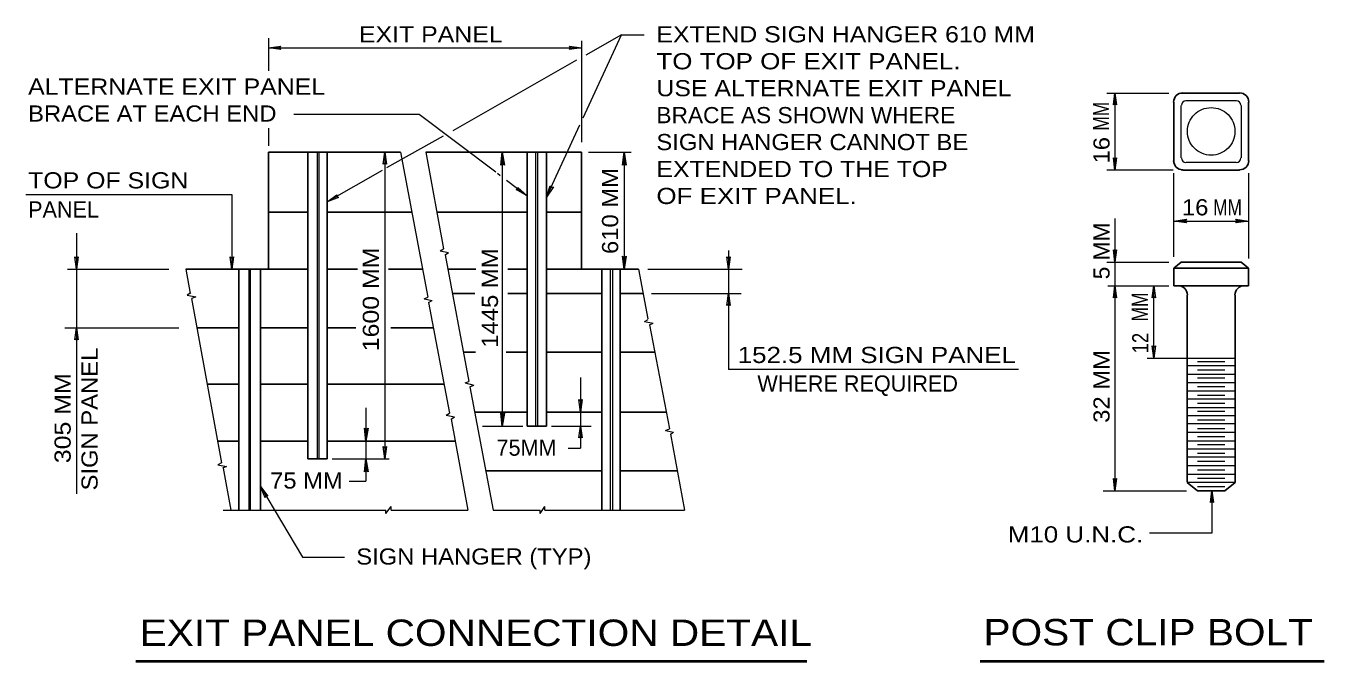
# Model space of a CAD drawing. Extents: x 312601.858 to 312602.699, y 144420.109 to 144420.704.
# Drawn here: x 312602.264 to 312602.5049, y 144420.2749 to 144420.3927 of the extents above; entities that cross this region are included whole.
import ezdxf
from ezdxf.enums import TextEntityAlignment as Align

# ---------------------------------------------------------------- set-up
doc = ezdxf.new("R2010")
doc.units = 0
doc.header["$LTSCALE"] = 0.0012
doc.linetypes.add('LONG_DASHED', pattern=[7.5, 6, -1.5])
for name, color, linetype, lineweight in [('1', 7, 'Continuous', 13), ('2', 7, 'Continuous', 13), ('39', 7, 'Continuous', 13)]:
    doc.layers.add(name, color=color, linetype=linetype, lineweight=lineweight)

msp = doc.modelspace()

# ---------------------------------------------------------------- hatches: boundary and pattern name
at = {"layer": '39'}
for points in [[(312602.3524, 144420.3671), (312602.3521, 144420.3669), (312602.3524, 144420.3693), (312602.3528, 144420.3669)], [(312602.375, 144420.3671), (312602.3747, 144420.3669), (312602.375, 144420.3693), (312602.3754, 144420.3669)], [(312602.4792, 144420.3565), (312602.4794, 144420.3562), (312602.477, 144420.3565), (312602.4794, 144420.3569)], [(312602.4887, 144420.3565), (312602.4885, 144420.3569), (312602.4909, 144420.3565), (312602.4885, 144420.3562)], [(312602.375, 144420.3498), (312602.3754, 144420.35), (312602.375, 144420.3476), (312602.3747, 144420.35)], [(312602.3524, 144420.3207), (312602.3528, 144420.3209), (312602.3524, 144420.3185), (312602.3521, 144420.3209)], [(312602.3271, 144420.3179), (312602.3275, 144420.3181), (312602.3271, 144420.3157), (312602.3268, 144420.3181)], [(312602.3271, 144420.3102), (312602.3268, 144420.31), (312602.3271, 144420.3124), (312602.3275, 144420.31)]]:
    msp.add_hatch(color=256, dxfattribs=at).paths.add_polyline_path(points)

# ---------------------------------------------------------------- linework, layer by layer
at = {"layer": '1'}
for p, q in [((312602.3674, 144420.3757), (312602.3745, 144420.3911)), ((312602.3745, 144420.3911), (312602.3679, 144420.3873)), ((312602.3745, 144420.3911), (312602.3787, 144420.3911)), ((312602.309, 144420.3905), (312602.309, 144420.3844)), ((312602.309, 144420.3887), (312602.3671, 144420.3887)), ((312602.3671, 144420.39), (312602.3671, 144420.3712)), ((312602.3662, 144420.3864), (312602.3432, 144420.3733)), ((312602.4646, 144420.3803), (312602.4761, 144420.3803)), ((312602.4661, 144420.3803), (312602.4661, 144420.366)), ((312602.4784, 144420.3803), (312602.4892, 144420.3803)), ((312602.4793, 144420.3789), (312602.4886, 144420.3789)), ((312602.4909, 144420.3787), (312602.4909, 144420.3674)), ((312602.3137, 144420.3764), (312602.337, 144420.3764)), ((312602.4784, 144420.3683), (312602.4784, 144420.378)), ((312602.4895, 144420.378), (312602.4895, 144420.3683)), ((312602.3606, 144420.361), (312602.3668, 144420.3744)), ((312602.309, 144420.3738), (312602.309, 144420.3705)), ((312602.3414, 144420.3723), (312602.3309, 144420.3664)), ((312602.3306, 144420.3693), (312602.3306, 144420.3124)), ((312602.3335, 144420.3693), (312602.3386, 144420.3424)), ((312602.3382, 144420.3693), (312602.3415, 144420.3514)), ((312602.3524, 144420.3693), (312602.3524, 144420.3185)), ((312602.3684, 144420.3693), (312602.3763, 144420.3693)), ((312602.375, 144420.3693), (312602.375, 144420.3476)), ((312602.4886, 144420.3674), (312602.4793, 144420.3674)), ((312602.3301, 144420.3659), (312602.3199, 144420.3601)), ((312602.4769, 144420.366), (312602.4646, 144420.366)), ((312602.477, 144420.3499), (312602.477, 144420.3654)), ((312602.4893, 144420.366), (312602.4784, 144420.366)), ((312602.4909, 144420.3654), (312602.4909, 144420.3496)), ((312602.264, 144420.3615), (312602.3022, 144420.3615)), ((312602.3022, 144420.3615), (312602.3022, 144420.3476)), ((312602.477, 144420.3565), (312602.4909, 144420.3565)), ((312602.3409, 144420.351), (312602.3415, 144420.3514)), ((312602.3409, 144420.351), (312602.3424, 144420.3507)), ((312602.3418, 144420.3503), (312602.3424, 144420.3507)), ((312602.3418, 144420.3503), (312602.3462, 144420.3268)), ((312602.3944, 144420.3511), (312602.3944, 144420.3431)), ((312602.2717, 144420.3476), (312602.2905, 144420.3476)), ((312602.2937, 144420.3476), (312602.2945, 144420.3431)), ((312602.3777, 144420.3476), (312602.3794, 144420.3384)), ((312602.3794, 144420.3476), (312602.3969, 144420.3476)), ((312602.4646, 144420.3489), (312602.4761, 144420.3489)), ((312602.3801, 144420.3431), (312602.3967, 144420.3431)), ((312602.3944, 144420.3431), (312602.3944, 144420.329)), ((312602.4648, 144420.3445), (312602.4761, 144420.3445)), ((312602.4733, 144420.3311), (312602.4733, 144420.3445)), ((312602.2947, 144420.3422), (312602.3003, 144420.3117)), ((312602.3379, 144420.3421), (312602.3386, 144420.3424)), ((312602.3379, 144420.3421), (312602.3394, 144420.3418)), ((312602.3387, 144420.3414), (312602.3394, 144420.3418)), ((312602.3387, 144420.3414), (312602.3426, 144420.3209)), ((312602.3788, 144420.3379), (312602.3795, 144420.3383)), ((312602.3788, 144420.3379), (312602.3804, 144420.3376)), ((312602.2712, 144420.3367), (312602.2924, 144420.3367)), ((312602.2734, 144420.3367), (312602.2734, 144420.3059)), ((312602.3797, 144420.3373), (312602.3804, 144420.3376)), ((312602.3797, 144420.3373), (312602.3834, 144420.318)), ((312602.4721, 144420.3311), (312602.4884, 144420.3311)), ((312602.4482, 144420.329), (312602.3944, 144420.329)), ((312602.4884, 144420.3297), (312602.4795, 144420.3297)), ((312602.4884, 144420.3281), (312602.4795, 144420.3281)), ((312602.4865, 144420.3304), (312602.4814, 144420.3304)), ((312602.4865, 144420.3289), (312602.4814, 144420.3289)), ((312602.3455, 144420.3265), (312602.3462, 144420.3268)), ((312602.3455, 144420.3265), (312602.3471, 144420.3261)), ((312602.3464, 144420.3258), (312602.3471, 144420.3261)), ((312602.3464, 144420.3258), (312602.3507, 144420.3029)), ((312602.4884, 144420.3265), (312602.4795, 144420.3265)), ((312602.4865, 144420.3274), (312602.4814, 144420.3274)), ((312602.4865, 144420.3258), (312602.4814, 144420.3258)), ((312602.4884, 144420.325), (312602.4795, 144420.325)), ((312602.4884, 144420.3235), (312602.4795, 144420.3235)), ((312602.4865, 144420.3242), (312602.4814, 144420.3242)), ((312602.342, 144420.3205), (312602.3426, 144420.3209)), ((312602.4884, 144420.3219), (312602.4795, 144420.3219)), ((312602.4865, 144420.3227), (312602.4814, 144420.3227)), ((312602.4865, 144420.3212), (312602.4814, 144420.3212)), ((312602.342, 144420.3205), (312602.3435, 144420.3202)), ((312602.3429, 144420.3198), (312602.3435, 144420.3202)), ((312602.3429, 144420.3198), (312602.346, 144420.3029)), ((312602.3487, 144420.3185), (312602.3562, 144420.3185)), ((312602.3615, 144420.3185), (312602.3689, 144420.3185)), ((312602.4884, 144420.3204), (312602.4795, 144420.3204)), ((312602.4884, 144420.3189), (312602.4795, 144420.3189)), ((312602.4865, 144420.3196), (312602.4814, 144420.3196)), ((312602.3827, 144420.3177), (312602.3834, 144420.318)), ((312602.3827, 144420.3177), (312602.3842, 144420.3174)), ((312602.3836, 144420.317), (312602.3842, 144420.3174)), ((312602.3836, 144420.317), (312602.3862, 144420.3029)), ((312602.4884, 144420.3173), (312602.4795, 144420.3173)), ((312602.4865, 144420.318), (312602.4814, 144420.318)), ((312602.4865, 144420.3165), (312602.4814, 144420.3165)), ((312602.4884, 144420.3157), (312602.4795, 144420.3157)), ((312602.4884, 144420.3142), (312602.4795, 144420.3142)), ((312602.4865, 144420.315), (312602.4814, 144420.315)), ((312602.3208, 144420.3124), (312602.3314, 144420.3124)), ((312602.3271, 144420.3124), (312602.3271, 144420.3083)), ((312602.4884, 144420.3127), (312602.4795, 144420.3127)), ((312602.4865, 144420.3134), (312602.4814, 144420.3134)), ((312602.4865, 144420.3119), (312602.4814, 144420.3119)), ((312602.3006, 144420.3107), (312602.302, 144420.3029)), ((312602.4884, 144420.3111), (312602.4795, 144420.3111)), ((312602.4884, 144420.3095), (312602.4795, 144420.3095)), ((312602.4865, 144420.3103), (312602.4814, 144420.3103)), ((312602.3075, 144420.3073), (312602.3153, 144420.2942)), ((312602.4639, 144420.3065), (312602.4794, 144420.3065)), ((312602.4884, 144420.308), (312602.4795, 144420.308)), ((312602.4865, 144420.3088), (312602.4814, 144420.3088)), ((312602.4865, 144420.3072), (312602.4814, 144420.3072)), ((312602.3006, 144420.3029), (312602.3308, 144420.3029)), ((312602.3308, 144420.3023), (312602.3318, 144420.3036)), ((312602.3308, 144420.3023), (312602.3308, 144420.3029)), ((312602.3318, 144420.3029), (312602.3318, 144420.3036)), ((312602.3318, 144420.3029), (312602.346, 144420.3029)), ((312602.3507, 144420.3029), (312602.3594, 144420.3029)), ((312602.3594, 144420.3023), (312602.3603, 144420.3036)), ((312602.3594, 144420.3023), (312602.3594, 144420.3029)), ((312602.3603, 144420.3029), (312602.3603, 144420.3036)), ((312602.3603, 144420.3029), (312602.3862, 144420.3029)), ((312602.3153, 144420.2942), (312602.3231, 144420.2942))]:
    msp.add_line(p, q, dxfattribs=at)
at = {"layer": '1', "lineweight": 25}
for p, q in [((312602.4787, 144420.3803), (312602.4892, 144420.3803)), ((312602.477, 144420.3676), (312602.477, 144420.3786)), ((312602.4909, 144420.3786), (312602.4909, 144420.3677)), ((312602.309, 144420.3693), (312602.309, 144420.3476)), ((312602.309, 144420.3693), (312602.3335, 144420.3693)), ((312602.3163, 144420.3693), (312602.3163, 144420.3124)), ((312602.3199, 144420.3693), (312602.3199, 144420.3124)), ((312602.3382, 144420.3693), (312602.3671, 144420.3693)), ((312602.357, 144420.3693), (312602.357, 144420.3185)), ((312602.3606, 144420.3693), (312602.3606, 144420.3185)), ((312602.3671, 144420.3693), (312602.3671, 144420.3476)), ((312602.4787, 144420.366), (312602.4892, 144420.366)), ((312602.309, 144420.3582), (312602.3163, 144420.3582)), ((312602.3199, 144420.3582), (312602.3356, 144420.3582)), ((312602.3403, 144420.3582), (312602.357, 144420.3582)), ((312602.3606, 144420.3582), (312602.3671, 144420.3582)), ((312602.2937, 144420.3476), (312602.3163, 144420.3476)), ((312602.3035, 144420.3476), (312602.3035, 144420.3029)), ((312602.3075, 144420.3476), (312602.3075, 144420.3029)), ((312602.3199, 144420.3476), (312602.3255, 144420.3476)), ((312602.3313, 144420.3476), (312602.3375, 144420.3476)), ((312602.3423, 144420.3476), (312602.3475, 144420.3476)), ((312602.3534, 144420.3476), (312602.357, 144420.3476)), ((312602.3606, 144420.3476), (312602.3777, 144420.3476)), ((312602.3709, 144420.3476), (312602.3709, 144420.3029)), ((312602.3743, 144420.3476), (312602.3743, 144420.3029)), ((312602.477, 144420.3478), (312602.4784, 144420.3489)), ((312602.477, 144420.3445), (312602.477, 144420.3478)), ((312602.477, 144420.3478), (312602.4909, 144420.3478)), ((312602.4784, 144420.3489), (312602.4895, 144420.3489)), ((312602.4895, 144420.3489), (312602.4909, 144420.3478)), ((312602.4909, 144420.3478), (312602.4909, 144420.3445)), ((312602.3431, 144420.3431), (312602.3473, 144420.3431)), ((312602.3534, 144420.3431), (312602.357, 144420.3431)), ((312602.3606, 144420.3431), (312602.3709, 144420.3431)), ((312602.3743, 144420.3431), (312602.3786, 144420.3431)), ((312602.477, 144420.3445), (312602.4909, 144420.3445)), ((312602.4795, 144420.3428), (312602.4795, 144420.3081)), ((312602.4884, 144420.3428), (312602.4884, 144420.308)), ((312602.2957, 144420.3367), (312602.3035, 144420.3367)), ((312602.3075, 144420.3367), (312602.3163, 144420.3367)), ((312602.3199, 144420.3367), (312602.3252, 144420.3367)), ((312602.3317, 144420.3367), (312602.3397, 144420.3367)), ((312602.3452, 144420.3322), (312602.3474, 144420.3322)), ((312602.3531, 144420.3322), (312602.357, 144420.3322)), ((312602.3606, 144420.3322), (312602.3709, 144420.3322)), ((312602.3743, 144420.3322), (312602.3806, 144420.3322)), ((312602.2976, 144420.3263), (312602.3035, 144420.3263)), ((312602.3075, 144420.3263), (312602.3163, 144420.3263)), ((312602.3199, 144420.3263), (312602.3416, 144420.3263)), ((312602.3473, 144420.3211), (312602.357, 144420.3211)), ((312602.3606, 144420.3211), (312602.3709, 144420.3211)), ((312602.3743, 144420.3211), (312602.3828, 144420.3211)), ((312602.357, 144420.3185), (312602.3606, 144420.3185)), ((312602.2996, 144420.3157), (312602.3035, 144420.3157)), ((312602.3075, 144420.3157), (312602.3163, 144420.3157)), ((312602.3199, 144420.3157), (312602.3437, 144420.3157)), ((312602.3163, 144420.3124), (312602.3199, 144420.3124)), ((312602.3494, 144420.3102), (312602.3709, 144420.3102)), ((312602.3743, 144420.3102), (312602.3849, 144420.3102)), ((312602.4814, 144420.3065), (312602.4795, 144420.308)), ((312602.4814, 144420.3065), (312602.4865, 144420.3065)), ((312602.4865, 144420.3065), (312602.4884, 144420.308))]:
    msp.add_line(p, q, dxfattribs=at)
at = {"layer": '1'}
for points in [[(312602.3113, 144420.3884), (312602.309, 144420.3887), (312602.3113, 144420.389), (312602.311, 144420.3887)], [(312602.3649, 144420.389), (312602.3671, 144420.3887), (312602.3649, 144420.3884), (312602.3651, 144420.3887)], [(312602.4658, 144420.3781), (312602.4661, 144420.3803), (312602.4664, 144420.3781), (312602.4661, 144420.3783)], [(312602.3303, 144420.3671), (312602.3306, 144420.3693), (312602.3309, 144420.3671), (312602.3306, 144420.3673)], [(312602.4664, 144420.3683), (312602.4661, 144420.366), (312602.4658, 144420.3683), (312602.4661, 144420.368)], [(312602.3553, 144420.3628), (312602.357, 144420.3612), (312602.355, 144420.3624), (312602.3554, 144420.3624)], [(312602.3619, 144420.3629), (312602.3606, 144420.361), (312602.3613, 144420.3631), (312602.3615, 144420.3628)], [(312602.322, 144420.3609), (312602.3199, 144420.3601), (312602.3217, 144420.3614), (312602.3217, 144420.3611)], [(312602.2737, 144420.3499), (312602.2734, 144420.3476), (312602.2731, 144420.3499), (312602.2734, 144420.3496)], [(312602.3025, 144420.3499), (312602.3022, 144420.3476), (312602.3019, 144420.3499), (312602.3022, 144420.3496)], [(312602.3947, 144420.3499), (312602.3944, 144420.3476), (312602.3941, 144420.3499), (312602.3944, 144420.3496)], [(312602.4664, 144420.3512), (312602.4661, 144420.3489), (312602.4658, 144420.3512), (312602.4661, 144420.3509)], [(312602.3941, 144420.3409), (312602.3944, 144420.3431), (312602.3947, 144420.3409), (312602.3944, 144420.3411)], [(312602.4658, 144420.3423), (312602.4661, 144420.3445), (312602.4664, 144420.3423), (312602.4661, 144420.3425)], [(312602.473, 144420.3423), (312602.4733, 144420.3445), (312602.4736, 144420.3423), (312602.4733, 144420.3425)], [(312602.2731, 144420.3345), (312602.2734, 144420.3367), (312602.2737, 144420.3345), (312602.2734, 144420.3347)], [(312602.4736, 144420.3334), (312602.4733, 144420.3311), (312602.473, 144420.3334), (312602.4733, 144420.3331)], [(312602.3672, 144420.3234), (312602.3669, 144420.3211), (312602.3666, 144420.3234), (312602.3669, 144420.3231)], [(312602.3666, 144420.3163), (312602.3669, 144420.3185), (312602.3672, 144420.3163), (312602.3669, 144420.3165)], [(312602.3309, 144420.3147), (312602.3306, 144420.3124), (312602.3303, 144420.3147), (312602.3306, 144420.3144)], [(312602.3084, 144420.3052), (312602.3075, 144420.3073), (312602.3089, 144420.3055), (312602.3085, 144420.3056)], [(312602.4664, 144420.3088), (312602.4661, 144420.3065), (312602.4658, 144420.3088), (312602.4661, 144420.3085)], [(312602.4838, 144420.3043), (312602.4841, 144420.3065), (312602.4844, 144420.3043), (312602.4841, 144420.3045)]]:
    msp.add_lwpolyline(points, close=True, dxfattribs=at)
for points in [[(312602.4661, 144420.357), (312602.4661, 144420.3489), (312602.4661, 144420.3445), (312602.4661, 144420.3065)], [(312602.2734, 144420.3543), (312602.2734, 144420.3476), (312602.2734, 144420.3367)], [(312602.3669, 144420.3275), (312602.3669, 144420.3211), (312602.3669, 144420.3185), (312602.3669, 144420.3144)], [(312602.3271, 144420.3219), (312602.3271, 144420.3157), (312602.3271, 144420.3124)], [(312602.4841, 144420.3065), (312602.4841, 144420.2986), (312602.4725, 144420.2986)]]:
    msp.add_lwpolyline(points, dxfattribs=at)
at = {"layer": '1', "linetype": 'LONG_DASHED'}
msp.add_circle((312602.483955, 144420.373185), 0.00442, dxfattribs=at)
at = {"layer": '1', "lineweight": 25}
for centre, start, end in [((312602.478685, 144420.378625), 90, 180), ((312602.489225, 144420.378625), 0, 90.00156), ((312602.478685, 144420.367745), 180, 270), ((312602.489225, 144420.367745), 270, 359.99844), ((312602.477835, 144420.342845), 0, 90), ((312602.490075, 144420.342845), 90, 180)]:
    msp.add_arc(centre, 0.0017, start, end, dxfattribs=at)
at = {"layer": '1'}
for centre, start, end in [((312602.47928, 144420.37803), 90, 180), ((312602.48863, 144420.37803), 0, 90), ((312602.47928, 144420.368255), 180, 270), ((312602.48863, 144420.368255), 270, 0)]:
    msp.add_arc(centre, 0.00085, start, end, dxfattribs=at)
at = {"layer": '2'}
for p, q in [((312602.337, 144420.3764), (312602.3512, 144420.3657)), ((312602.3515, 144420.3654), (312602.352, 144420.365)), ((312602.3532, 144420.3641), (312602.357, 144420.3612)), ((312602.3646, 144420.3144), (312602.3669, 144420.3144)), ((312602.324, 144420.3083), (312602.3271, 144420.3083))]:
    msp.add_line(p, q, dxfattribs=at)
at = {"layer": '2', "linetype": 'LONG_DASHED'}
for p, q in [((312602.3181, 144420.3124), (312602.3181, 144420.3693)), ((312602.3184, 144420.3124), (312602.3184, 144420.3693)), ((312602.3586, 144420.3184), (312602.3586, 144420.3693)), ((312602.359, 144420.3185), (312602.359, 144420.3693)), ((312602.3054, 144420.3029), (312602.3054, 144420.3476)), ((312602.3057, 144420.3029), (312602.3057, 144420.3476)), ((312602.3725, 144420.3029), (312602.3725, 144420.3476)), ((312602.3729, 144420.3029), (312602.3729, 144420.3476))]:
    msp.add_line(p, q, dxfattribs=at)
at = {"layer": '2', "lineweight": 40}
for p, q in [((312602.2844, 144420.2749), (312602.4089, 144420.2749)), ((312602.4411, 144420.2749), (312602.5049, 144420.2749))]:
    msp.add_line(p, q, dxfattribs=at)
at = {"layer": '2'}
for points in [[(312602.2946, 144420.3432), (312602.2939, 144420.3428), (312602.2955, 144420.3425), (312602.2948, 144420.3422)], [(312602.3003, 144420.3117), (312602.2996, 144420.3113), (312602.3012, 144420.311), (312602.3005, 144420.3107)]]:
    msp.add_lwpolyline(points, dxfattribs=at)
at = {"layer": '39'}
for points in [[(312602.3524, 144420.3671), (312602.3521, 144420.3669), (312602.3524, 144420.3693), (312602.3528, 144420.3669)], [(312602.375, 144420.3671), (312602.3747, 144420.3669), (312602.375, 144420.3693), (312602.3754, 144420.3669)], [(312602.4792, 144420.3565), (312602.4794, 144420.3562), (312602.477, 144420.3565), (312602.4794, 144420.3569)], [(312602.4887, 144420.3565), (312602.4885, 144420.3569), (312602.4909, 144420.3565), (312602.4885, 144420.3562)], [(312602.375, 144420.3498), (312602.3754, 144420.35), (312602.375, 144420.3476), (312602.3747, 144420.35)], [(312602.3524, 144420.3207), (312602.3528, 144420.3209), (312602.3524, 144420.3185), (312602.3521, 144420.3209)], [(312602.3271, 144420.3179), (312602.3275, 144420.3181), (312602.3271, 144420.3157), (312602.3268, 144420.3181)], [(312602.3271, 144420.3102), (312602.3268, 144420.31), (312602.3271, 144420.3124), (312602.3275, 144420.31)]]:
    msp.add_lwpolyline(points, close=True, dxfattribs=at)

# ---------------------------------------------------------------- texts
at = {"layer": '2'}
for s, height, width, p in [('EXIT PANEL', 0.003, 1.15, (312602.3258, 144420.3897)), ('EXTEND SIGN HANGER 610 MM', 0.003, 1.15, (312602.381, 144420.3897)), ('TO TOP OF EXIT PANEL.', 0.003, 1.2, (312602.381, 144420.3847)), ('ALTERNATE EXIT PANEL', 0.003, 1.15, (312602.2644, 144420.38)), ('USE ALTERNATE EXIT PANEL', 0.003, 1.15, (312602.381, 144420.3797)), ('BRACE AT EACH END', 0.003, 1.1, (312602.2644, 144420.375)), ('BRACE AS SHOWN WHERE', 0.003, 1.05, (312602.381, 144420.3747)), ('SIGN HANGER CANNOT BE', 0.003, 1.1, (312602.381, 144420.3697)), ('EXTENDED TO THE TOP', 0.003, 1.15, (312602.381, 144420.3647)), ('TOP OF SIGN', 0.003, 1.15, (312602.2644, 144420.3626)), ('OF EXIT PANEL.', 0.003, 1.2, (312602.381, 144420.3597)), ('M10 U.N.C.', 0.003, 1.2, (312602.4462, 144420.2969)), ('SIGN HANGER (TYP)', 0.003, 1.1, (312602.3253, 144420.2928)), ('EXIT PANEL CONNECTION DETAIL', 0.0049, 1.15, (312602.2851, 144420.2777)), ('POST CLIP BOLT', 0.0049, 1.15, (312602.4417, 144420.2778))]:
    msp.add_text(s, height=height, dxfattribs=dict(at, width=width)).set_placement(p)
for s, width, p in [('MM', 0.8, (312602.465, 144420.376)), ('16 ', 1.1, (312602.4651, 144420.3703)), ('610 MM', 1.1, (312602.3739, 144420.3584)), ('5 MM', 1.05, (312602.4651, 144420.351)), ('1600 MM', 1.15, (312602.3295, 144420.342)), ('1445 MM', 1.1, (312602.3516, 144420.34225)), ('MM', 0.8, (312602.4722, 144420.3406)), ('12', 0.85, (312602.4723, 144420.3339)), ('SIGN PANEL', 1.1, (312602.2773, 144420.3198)), ('32 MM', 1.1, (312602.4651, 144420.32585)), ('305 MM', 1.15, (312602.2723, 144420.31995))]:
    msp.add_text(s, height=0.003, rotation=90, dxfattribs=dict(at, width=width)).set_placement(p, align=Align.CENTER)
msp.add_text('PANEL', height=0.003, dxfattribs=at).set_placement((312602.2644, 144420.3572))
for s, width, p in [('16 ', 1.1, (312602.4816, 144420.3576)), ('MM', 0.8, (312602.487, 144420.3576)), ('152.5 MM SIGN PANEL', 1.2, (312602.4219, 144420.3302)), ('75 MM', 1.1, (312602.31605, 144420.3069))]:
    msp.add_text(s, height=0.003, dxfattribs=dict(at, width=width)).set_placement(p, align=Align.CENTER)
for s, p in [('WHERE REQUIRED', (312602.41835, 144420.3249)), ('75MM', (312602.3569, 144420.313))]:
    msp.add_text(s, height=0.003, dxfattribs=at).set_placement(p, align=Align.CENTER)

doc.saveas('drawing.dxf')
